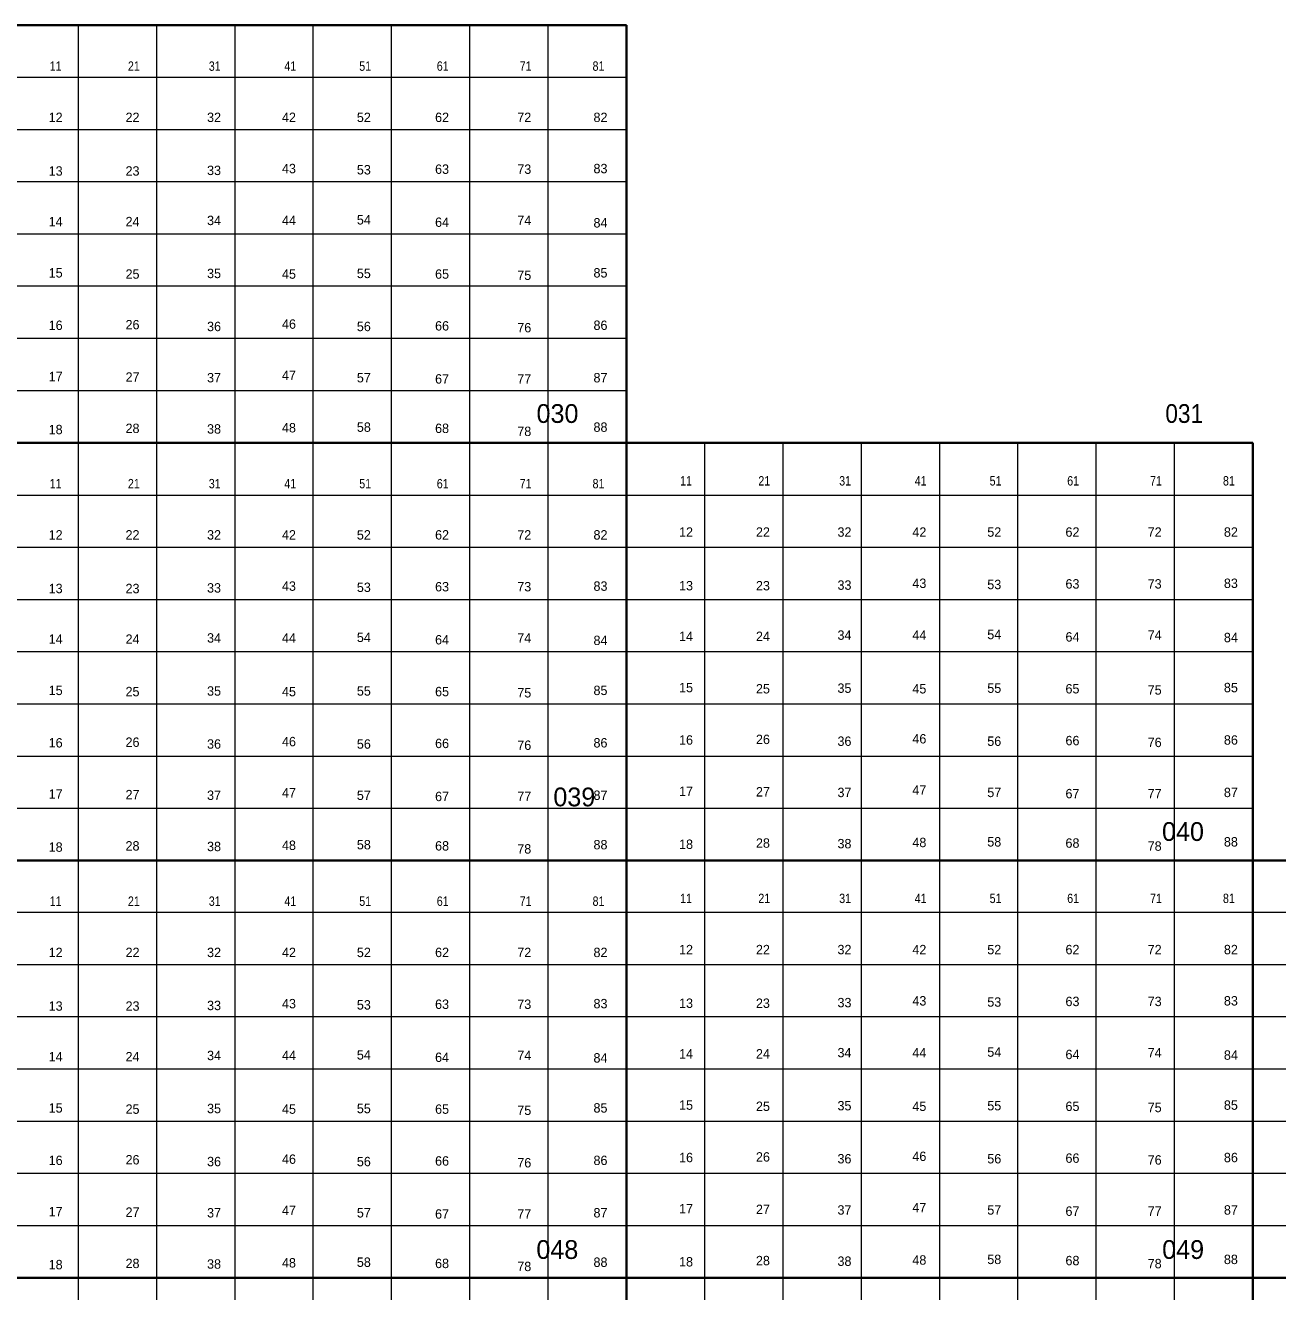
# Model space of a CAD drawing. Extents: x 639000 to 672000, y 222000 to 252000.
# Drawn here: x 660121 to 666119, y 239934 to 246000 of the extents above; entities that cross this region are included whole.
import ezdxf
from ezdxf.enums import TextEntityAlignment as Align

# ---------------------------------------------------------------- set-up
doc = ezdxf.new("R2010")
doc.units = 0
doc.header["$LTSCALE"] = 18
doc.layers.add('1', color=7, linetype='Continuous', lineweight=13)
doc.layers.add('2', color=7, linetype='Continuous')
doc.layers.add('29', color=7, linetype='Continuous')

msp = doc.modelspace()

# ---------------------------------------------------------------- linework, layer by layer
at = {"layer": '1', "lineweight": 35}
for p, q in [((639000, 246000), (663000, 246000)), ((663000, 224000), (663000, 246000)), ((666000, 244000), (639000, 244000)), ((666000, 230000), (666000, 244000)), ((639000, 242000), (672000, 242000)), ((672000, 240000), (639000, 240000))]:
    msp.add_line(p, q, dxfattribs=at)
at = {"layer": '1'}
for p, q in [((660375, 224000), (660375, 246000)), ((660750, 224000), (660750, 246000)), ((661125, 224000), (661125, 246000)), ((661500, 224000), (661500, 246000)), ((661875, 224000), (661875, 246000)), ((662250, 224000), (662250, 246000)), ((662625, 224000), (662625, 246000)), ((663000, 245750), (639000, 245750)), ((663000, 245500), (639000, 245500)), ((663000, 245250), (639000, 245250)), ((663000, 245000), (639000, 245000)), ((663000, 244750), (639000, 244750)), ((663000, 244500), (639000, 244500)), ((663000, 244250), (639000, 244250)), ((663375, 230000), (663375, 244000)), ((663750, 230000), (663750, 244000)), ((664125, 230000), (664125, 244000)), ((664500, 230000), (664500, 244000)), ((664875, 230000), (664875, 244000)), ((665250, 230000), (665250, 244000)), ((665625, 230000), (665625, 244000)), ((639000, 243750), (666000, 243750)), ((639000, 243500), (666000, 243500)), ((639000, 243250), (666000, 243250)), ((639000, 243000), (666000, 243000)), ((639000, 242750), (666000, 242750)), ((639000, 242500), (666000, 242500)), ((639000, 242250), (666000, 242250)), ((672000, 241750), (639000, 241750)), ((672000, 241500), (639000, 241500)), ((672000, 241250), (639000, 241250)), ((672000, 241000), (639000, 241000)), ((672000, 240750), (639000, 240750)), ((672000, 240500), (639000, 240500)), ((672000, 240250), (639000, 240250))]:
    msp.add_line(p, q, dxfattribs=at)

# ---------------------------------------------------------------- texts
at = {"layer": '2'}
for s, p in [('030', (662669.47, 244095.54)), ('039', (662750.04, 242259.03)), ('040', (665665.2, 242093.33)), ('048', (662668.65, 240091.12)), ('049', (665666.02, 240091.12))]:
    msp.add_text(s, height=90, rotation=359.94, dxfattribs=at).set_placement(p, align=Align.CENTER)
at = {"layer": '2', "width": 0.9}
msp.add_text('031', height=90, rotation=359.94, dxfattribs=at).set_placement((665671.16, 244095.54), align=Align.CENTER)
at = {"layer": '29', "width": 0.85}
for s, p in [('11', (660265.92, 245782.2)), ('21', (660640.53, 245782.2)), ('31', (661027.83, 245782.2)), ('41', (661389.73, 245782.2)), ('51', (661748.47, 245782.2)), ('61', (662119.89, 245782.2)), ('71', (662516.72, 245782.2)), ('81', (662865.93, 245782.2)), ('11', (660265.92, 243782.2)), ('21', (660640.53, 243782.2)), ('31', (661027.83, 243782.2)), ('41', (661389.73, 243782.2)), ('51', (661748.47, 243782.2)), ('61', (662119.89, 243782.2)), ('71', (662516.72, 243782.2)), ('81', (662865.93, 243782.2)), ('11', (663285.22, 243795.72)), ('21', (663659.82, 243795.72)), ('31', (664047.12, 243795.72)), ('41', (664409.03, 243795.72)), ('51', (664767.76, 243795.72)), ('61', (665139.19, 243795.72)), ('71', (665536.02, 243795.72)), ('81', (665885.22, 243795.72)), ('11', (660265.92, 241782.2)), ('21', (660640.53, 241782.2)), ('31', (661027.83, 241782.2)), ('41', (661389.73, 241782.2)), ('51', (661748.47, 241782.2)), ('61', (662119.89, 241782.2)), ('71', (662516.72, 241782.2)), ('81', (662865.93, 241782.2)), ('11', (663285.22, 241795.72)), ('21', (663659.82, 241795.72)), ('31', (664047.12, 241795.72)), ('41', (664409.03, 241795.72)), ('51', (664767.76, 241795.72)), ('61', (665139.19, 241795.72)), ('71', (665536.02, 241795.72)), ('81', (665885.22, 241795.72))]:
    msp.add_text(s, height=45, dxfattribs=at).set_placement(p, align=Align.CENTER)
at = {"layer": '29'}
for s, p in [('12', (660265.92, 245536.81)), ('22', (660634.18, 245536.81)), ('32', (661024.65, 245536.81)), ('42', (661383.38, 245536.81)), ('52', (661742.11, 245536.81)), ('62', (662116.72, 245536.81)), ('72', (662510.37, 245536.81)), ('82', (662875.45, 245536.81)), ('13', (660265.92, 245279.87)), ('23', (660634.18, 245279.87)), ('33', (661024.65, 245282.76)), ('43', (661383.39, 245291.42)), ('53', (661742.11, 245285.65)), ('63', (662116.72, 245288.53)), ('73', (662510.37, 245288.53)), ('83', (662875.45, 245291.42)), ('14', (660265.92, 245037.37)), ('24', (660634.18, 245037.37)), ('34', (661024.65, 245043.14)), ('44', (661383.39, 245043.14)), ('54', (661742.11, 245046.03)), ('64', (662116.72, 245034.48)), ('74', (662510.37, 245043.14)), ('84', (662875.45, 245031.6)), ('15', (660265.92, 244791.98)), ('25', (660634.18, 244786.21)), ('35', (661024.65, 244789.09)), ('45', (661383.39, 244786.21)), ('55', (661742.11, 244789.09)), ('65', (662116.72, 244786.21)), ('75', (662510.37, 244780.43)), ('85', (662875.45, 244791.98)), ('16', (660265.92, 244540.82)), ('26', (660634.18, 244543.7)), ('36', (661024.65, 244535.04)), ('46', (661383.39, 244546.59)), ('56', (661742.11, 244535.04)), ('66', (662116.72, 244537.93)), ('76', (662510.37, 244529.27)), ('86', (662875.45, 244540.82)), ('17', (660265.92, 244295.43)), ('27', (660634.18, 244292.54)), ('37', (661024.65, 244289.65)), ('47', (661383.39, 244301.2)), ('57', (661742.12, 244289.65)), ('87', (662875.45, 244289.65)), ('67', (662116.72, 244283.88)), ('77', (662510.37, 244283.88)), ('18', (660265.92, 244041.37)), ('28', (660634.18, 244047.15)), ('38', (661024.65, 244044.26)), ('48', (661383.38, 244050.03)), ('58', (661742.11, 244052.92)), ('68', (662116.72, 244047.15)), ('88', (662875.45, 244052.92)), ('78', (662510.37, 244032.71)), ('12', (660265.92, 243536.81)), ('22', (660634.18, 243536.81)), ('32', (661024.65, 243536.81)), ('42', (661383.38, 243536.81)), ('52', (661742.11, 243536.81)), ('62', (662116.72, 243536.81)), ('72', (662510.37, 243536.81)), ('82', (662875.45, 243536.81)), ('12', (663285.22, 243550.33)), ('22', (663653.47, 243550.33)), ('32', (664043.95, 243550.33)), ('42', (664402.68, 243550.33)), ('52', (664761.41, 243550.33)), ('62', (665136.01, 243550.33)), ('72', (665529.66, 243550.33)), ('82', (665894.74, 243550.33)), ('13', (660265.92, 243279.87)), ('23', (660634.18, 243279.87)), ('33', (661024.65, 243282.76)), ('43', (661383.39, 243291.42)), ('53', (661742.11, 243285.65)), ('63', (662116.72, 243288.53)), ('73', (662510.37, 243288.53)), ('83', (662875.45, 243291.42)), ('13', (663285.22, 243293.4)), ('23', (663653.47, 243293.4)), ('33', (664043.95, 243296.28)), ('43', (664402.68, 243304.94)), ('53', (664761.41, 243299.17)), ('63', (665136.01, 243302.06)), ('73', (665529.67, 243302.06)), ('83', (665894.74, 243304.94)), ('14', (660265.92, 243037.37)), ('24', (660634.18, 243037.37)), ('34', (661024.65, 243043.14)), ('44', (661383.39, 243043.14)), ('54', (661742.11, 243046.03)), ('64', (662116.72, 243034.48)), ('74', (662510.37, 243043.14)), ('84', (662875.45, 243031.6)), ('14', (663285.22, 243050.89)), ('24', (663653.47, 243050.89)), ('34', (664043.95, 243056.67)), ('44', (664402.68, 243056.67)), ('54', (664761.41, 243059.55)), ('64', (665136.01, 243048.01)), ('74', (665529.67, 243056.67)), ('84', (665894.74, 243045.12)), ('15', (660265.92, 242791.98)), ('25', (660634.18, 242786.21)), ('35', (661024.65, 242789.09)), ('45', (661383.39, 242786.21)), ('55', (661742.11, 242789.09)), ('65', (662116.72, 242786.21)), ('75', (662510.37, 242780.43)), ('85', (662875.45, 242791.98)), ('15', (663285.22, 242805.5)), ('25', (663653.47, 242799.73)), ('35', (664043.95, 242802.61)), ('45', (664402.68, 242799.73)), ('55', (664761.41, 242802.61)), ('65', (665136.01, 242799.73)), ('75', (665529.67, 242793.95)), ('85', (665894.74, 242805.5)), ('16', (660265.92, 242540.82)), ('26', (660634.18, 242543.7)), ('36', (661024.65, 242535.04)), ('46', (661383.39, 242546.59)), ('56', (661742.11, 242535.04)), ('66', (662116.72, 242537.93)), ('76', (662510.37, 242529.27)), ('86', (662875.45, 242540.82)), ('16', (663285.22, 242554.34)), ('26', (663653.47, 242557.22)), ('36', (664043.95, 242548.56)), ('46', (664402.68, 242560.11)), ('56', (664761.41, 242548.56)), ('66', (665136.01, 242551.45)), ('76', (665529.67, 242542.79)), ('86', (665894.74, 242554.34)), ('17', (660265.92, 242295.43)), ('27', (660634.18, 242292.54)), ('37', (661024.65, 242289.65)), ('47', (661383.39, 242301.2)), ('57', (661742.12, 242289.65)), ('67', (662116.72, 242283.88)), ('77', (662510.37, 242283.88)), ('87', (662875.45, 242289.65)), ('17', (663285.22, 242308.95)), ('27', (663653.47, 242306.06)), ('37', (664043.95, 242303.17)), ('47', (664402.68, 242314.72)), ('57', (664761.41, 242303.17)), ('67', (665136.01, 242297.4)), ('77', (665529.67, 242297.4)), ('87', (665894.75, 242303.17)), ('18', (660265.92, 242041.37)), ('28', (660634.18, 242047.15)), ('38', (661024.65, 242044.26)), ('48', (661383.38, 242050.03)), ('58', (661742.11, 242052.92)), ('68', (662116.72, 242047.15)), ('88', (662875.45, 242052.92)), ('18', (663285.22, 242054.9)), ('28', (663653.47, 242060.67)), ('38', (664043.95, 242057.78)), ('48', (664402.68, 242063.56)), ('58', (664761.41, 242066.44)), ('68', (665136.01, 242060.67)), ('78', (665529.66, 242046.23)), ('88', (665894.74, 242066.44)), ('78', (662510.37, 242032.71)), ('12', (660265.92, 241536.81)), ('22', (660634.18, 241536.81)), ('32', (661024.65, 241536.81)), ('42', (661383.38, 241536.81)), ('52', (661742.11, 241536.81)), ('62', (662116.72, 241536.81)), ('72', (662510.37, 241536.81)), ('82', (662875.45, 241536.81)), ('12', (663285.22, 241550.33)), ('22', (663653.47, 241550.33)), ('32', (664043.95, 241550.33)), ('42', (664402.68, 241550.33)), ('52', (664761.41, 241550.33)), ('62', (665136.01, 241550.33)), ('72', (665529.66, 241550.33)), ('82', (665894.74, 241550.33)), ('13', (660265.92, 241279.87)), ('23', (660634.18, 241279.87)), ('33', (661024.65, 241282.76)), ('43', (661383.39, 241291.42)), ('53', (661742.11, 241285.65)), ('63', (662116.72, 241288.53)), ('73', (662510.37, 241288.53)), ('83', (662875.45, 241291.42)), ('13', (663285.22, 241293.4)), ('23', (663653.47, 241293.4)), ('33', (664043.95, 241296.28)), ('43', (664402.68, 241304.94)), ('53', (664761.41, 241299.17)), ('63', (665136.01, 241302.06)), ('73', (665529.67, 241302.06)), ('83', (665894.74, 241304.94)), ('14', (660265.92, 241037.37)), ('24', (660634.18, 241037.37)), ('34', (661024.65, 241043.14)), ('44', (661383.39, 241043.14)), ('54', (661742.11, 241046.03)), ('64', (662116.72, 241034.48)), ('74', (662510.37, 241043.14)), ('84', (662875.45, 241031.6)), ('14', (663285.22, 241050.89)), ('24', (663653.47, 241050.89)), ('34', (664043.95, 241056.67)), ('44', (664402.68, 241056.67)), ('54', (664761.41, 241059.55)), ('64', (665136.01, 241048.01)), ('74', (665529.67, 241056.67)), ('84', (665894.74, 241045.12)), ('15', (660265.92, 240791.98)), ('25', (660634.18, 240786.21)), ('35', (661024.65, 240789.09)), ('45', (661383.39, 240786.21)), ('55', (661742.11, 240789.09)), ('65', (662116.72, 240786.21)), ('75', (662510.37, 240780.43)), ('85', (662875.45, 240791.98)), ('15', (663285.22, 240805.5)), ('25', (663653.47, 240799.73)), ('35', (664043.95, 240802.61)), ('45', (664402.68, 240799.73)), ('55', (664761.41, 240802.61)), ('65', (665136.01, 240799.73)), ('75', (665529.67, 240793.95)), ('85', (665894.74, 240805.5)), ('16', (660265.92, 240540.82)), ('26', (660634.18, 240543.7)), ('36', (661024.65, 240535.04)), ('46', (661383.39, 240546.59)), ('56', (661742.11, 240535.04)), ('66', (662116.72, 240537.93)), ('76', (662510.37, 240529.27)), ('86', (662875.45, 240540.82)), ('16', (663285.22, 240554.34)), ('26', (663653.47, 240557.22)), ('36', (664043.95, 240548.56)), ('46', (664402.68, 240560.11)), ('56', (664761.41, 240548.56)), ('66', (665136.01, 240551.45)), ('76', (665529.67, 240542.79)), ('86', (665894.74, 240554.34)), ('17', (660265.92, 240295.43)), ('27', (660634.18, 240292.54)), ('37', (661024.65, 240289.65)), ('47', (661383.39, 240301.2)), ('57', (661742.12, 240289.65)), ('67', (662116.72, 240283.88)), ('77', (662510.37, 240283.88)), ('87', (662875.45, 240289.65)), ('17', (663285.22, 240308.95)), ('27', (663653.47, 240306.06)), ('37', (664043.95, 240303.17)), ('47', (664402.68, 240314.72)), ('57', (664761.41, 240303.17)), ('67', (665136.01, 240297.4)), ('77', (665529.67, 240297.4)), ('87', (665894.75, 240303.17)), ('18', (660265.92, 240041.37)), ('28', (660634.18, 240047.15)), ('38', (661024.65, 240044.26)), ('48', (661383.38, 240050.03)), ('58', (661742.11, 240052.92)), ('68', (662116.72, 240047.15)), ('88', (662875.45, 240052.92)), ('18', (663285.22, 240054.9)), ('28', (663653.47, 240060.67)), ('38', (664043.95, 240057.78)), ('48', (664402.68, 240063.56)), ('58', (664761.41, 240066.44)), ('68', (665136.01, 240060.67)), ('78', (665529.66, 240046.23)), ('88', (665894.74, 240066.44)), ('78', (662510.37, 240032.71))]:
    msp.add_text(s, height=45, dxfattribs=at).set_placement(p, align=Align.CENTER)

doc.saveas('drawing.dxf')
